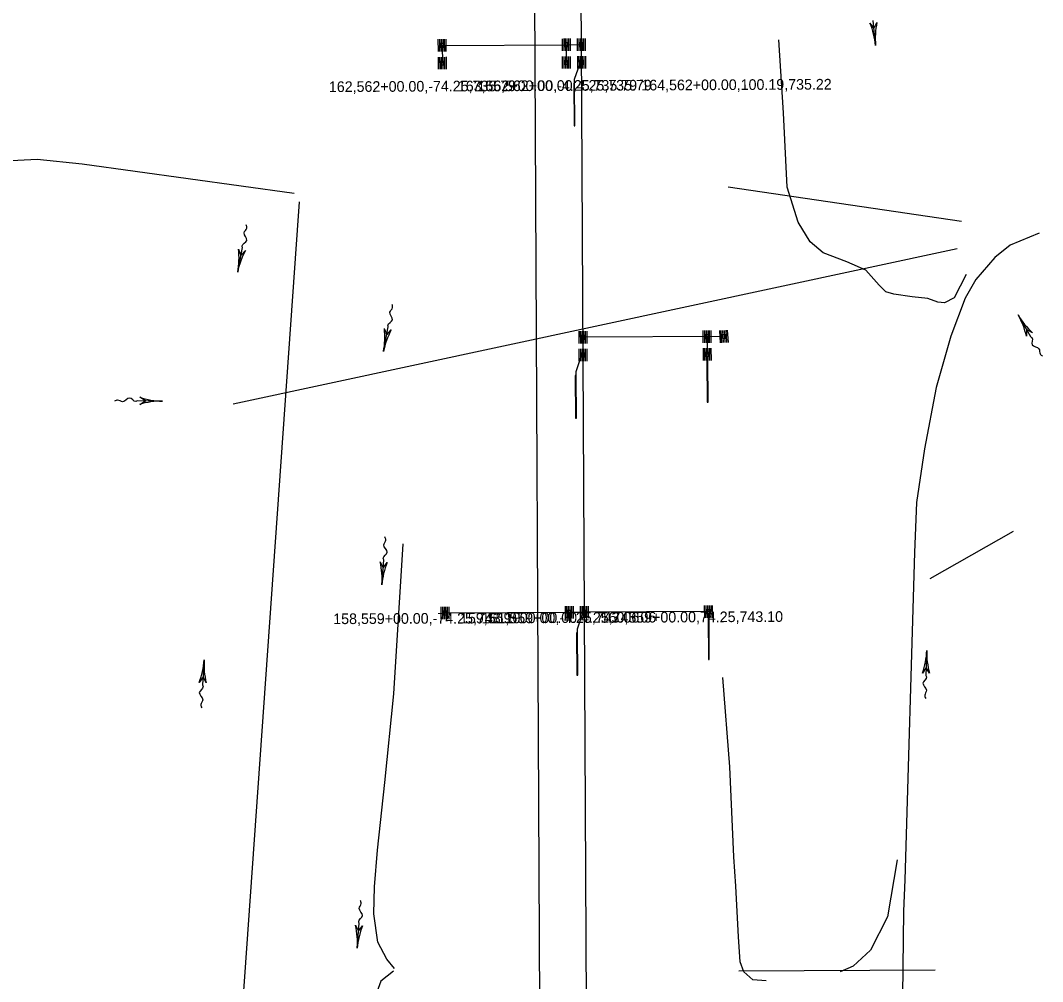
# Model space of a CAD drawing. Extents: x 593481 to 595859, y 101157 to 225994.
# Drawn here: x 594039 to 594615, y 154967 to 155509 of the extents above; entities that cross this region are included whole.
import ezdxf

# ---------------------------------------------------------------- set-up
doc = ezdxf.new("R2010")
doc.units = 0
for name, color, linetype in [('Default', 7, 'Continuous'), ('E_DTM_SpotElev', 7, 'Continuous'), ('E_PROF_GridMin', 7, 'Continuous'), ('Level 6', 7, 'Continuous'), ('P_DRN_SS_UG', 7, 'Continuous'), ('P_MAP_ContoursInter', 7, 'Continuous')]:
    doc.layers.add(name, color=color, linetype=linetype)

msp = doc.modelspace()

# ---------------------------------------------------------------- linework, layer by layer
at = {"layer": 'Default'}
msp.add_line((594334.5, 154382.75), (594308.82, 159385.62), dxfattribs=at)
at = {"layer": 'E_DTM_SpotElev'}
for p, q in [((594520.8, 155494.83), (594519.46, 155508.9)), ((594161.19, 155367.03), (594163.89, 155380.89)), ((594601.12, 155342.88), (594608.19, 155330.65)), ((594243.38, 155322.25), (594246.08, 155336.12)), ((594118.75, 155294.28), (594104.62, 155294.42)), ((594242.48, 155190.75), (594243.54, 155204.84)), ((594549.65, 155153.69), (594549.17, 155139.57)), ((594142.3, 155148.35), (594141.41, 155134.25)), ((594228.61, 154985.82), (594229.67, 154999.91))]:
    msp.add_line(p, q, dxfattribs=at)
for points in [[(594517.6, 155507.38), (594519.89, 155504.38), (594521.58, 155507.76)], [(594161.67, 155379.97), (594163.02, 155376.45), (594165.59, 155379.21)], [(594243.86, 155335.19), (594245.21, 155331.67), (594247.79, 155334.43)], [(594609.26, 155332.81), (594605.93, 155334.58), (594605.8, 155330.8)], [(594105.94, 155292.41), (594109.16, 155294.38), (594105.97, 155296.41)], [(594241.45, 155203.66), (594243.2, 155200.32), (594245.44, 155203.37)], [(594551.21, 155140.83), (594549.32, 155144.1), (594547.22, 155140.96)], [(594143.49, 155135.45), (594141.7, 155138.77), (594139.5, 155135.7)], [(594227.57, 154998.73), (594229.32, 154995.39), (594231.56, 154998.44)]]:
    msp.add_lwpolyline(points, dxfattribs=at)
for centre, start, end in [((594479.03, 155490.87), 5.41261, 23.17493), ((594562.57, 155498.79), 167.65029, 185.41261), ((594120, 155375.03), 349.00666, 6.76898), ((594202.38, 155359.02), 151.24434, 169.00666), ((594637.44, 155363.89), 210.05001, 227.81233), ((594564.8, 155321.87), 12.2877, 30.05001), ((594202.2, 155330.25), 349.00666, 6.76898), ((594284.57, 155314.25), 151.24434, 169.00666), ((594118.34, 155252.33), 89.4352, 107.19752), ((594119.17, 155336.24), 251.67288, 269.4352), ((594200.65, 155193.9), 355.6942, 13.45652), ((594284.32, 155187.6), 157.93188, 175.6942), ((594507.72, 155155.12), 340.28381, 358.04613), ((594591.58, 155152.26), 178.04613, 195.80845), ((594100.43, 155151), 338.61546, 356.37778), ((594184.17, 155145.7), 176.37778, 194.1401), ((594186.77, 154988.97), 355.6942, 13.45652), ((594270.44, 154982.67), 157.93188, 175.6942)]:
    msp.add_arc(centre, 41.96, start, end, dxfattribs=at)
for points in [[(594163.89, 155380.9), (594163.73, 155381.73), (594166.26, 155384.91), (594164.86, 155389.18), (594166.32, 155391.78), (594166.03, 155393.59)], [(594246.08, 155336.12), (594245.92, 155336.95), (594248.46, 155340.13), (594247.05, 155344.4), (594248.51, 155347), (594248.22, 155348.81)], [(594608.19, 155330.65), (594608.86, 155330.13), (594609.04, 155326.06), (594612.9, 155323.76), (594613.5, 155320.85), (594614.91, 155319.67)], [(594104.62, 155294.42), (594103.84, 155294.12), (594100.24, 155296.03), (594096.3, 155293.88), (594093.48, 155294.85), (594091.75, 155294.24)], [(594243.54, 155204.84), (594243.29, 155205.65), (594245.44, 155209.11), (594243.54, 155213.19), (594244.69, 155215.93), (594244.2, 155217.7)], [(594549.17, 155139.57), (594549.45, 155138.77), (594547.45, 155135.23), (594549.51, 155131.23), (594548.47, 155128.44), (594549.04, 155126.69)], [(594141.41, 155134.25), (594141.67, 155133.44), (594139.56, 155129.96), (594141.51, 155125.9), (594140.39, 155123.14), (594140.91, 155121.38)], [(594229.67, 154999.91), (594229.41, 155000.72), (594231.56, 155004.18), (594229.67, 155008.26), (594230.82, 155011), (594230.32, 155012.77)]]:
    msp.add_spline(points, degree=3, dxfattribs=at)
at = {"layer": 'E_PROF_GridMin'}
for p, q in [((594355.04, 155495.24), (594353.62, 155771.98)), ((594276.54, 155494.84), (594346.54, 155495.2)), ((594276.54, 155494.84), (594276.59, 155484.84)), ((594346.54, 155495.2), (594355.04, 155495.24)), ((594346.59, 155485.2), (594346.54, 155495.2)), ((594356.68, 155175.25), (594355.04, 155495.24)), ((594434.34, 155330.65), (594355.89, 155330.24)), ((594425.94, 155330.6), (594425.94, 155320.6)), ((594425.96, 155319.64), (594425.97, 155317.64)), ((594278.18, 155174.84), (594348.18, 155175.2)), ((594348.18, 155175.2), (594356.68, 155175.25)), ((594426.68, 155175.61), (594356.68, 155175.25)), ((594358.22, 154875.25), (594356.68, 155175.25)), ((594426.69, 155174.61), (594426.7, 155172.61))]:
    msp.add_line(p, q, dxfattribs=at)
for points in [[(594571.92, 155365.74), (594565.14, 155352.43), (594559.64, 155349.73), (594555.87, 155350.12), (594550.25, 155352.04), (594541.37, 155353.15), (594531.15, 155354.6), (594526.59, 155355.9), (594522.9, 155359.56), (594515.29, 155368.06), (594504.61, 155372.79), (594491.24, 155377.87), (594483.84, 155384), (594477.1, 155395.15), (594470.86, 155414.95), (594468.94, 155456.73), (594466.21, 155498.03)], [(594353.8, 155484.07), (594350.89, 155475.55), (594350.9, 155473.55)], [(594193.09, 155411.34), (594073.54, 155427.86), (594048.1, 155430.58), (594022.56, 155429.15), (594004.52, 155425.45), (593990.2, 155419.58), (593976.72, 155409.53), (593963.18, 155397.41), (593953.35, 155382.07), (593943.75, 155338.68), (593941.24, 155313.82), (593931.56, 155304.71), (593921.12, 155302.9), (593896.63, 155305.59), (593891.96, 155307.79), (593879.74, 155310.17), (593860.02, 155314.83), (593844.02, 155317.31), (593827.14, 155321.89), (593814.99, 155327.39)], [(594195.87, 155406.63), (594155.86, 154839.17), (594136.12, 154647.32), (594125.75, 154586.3), (594119.28, 154562.31), (594104.8, 154521.76), (594093.35, 154507.25), (594075.71, 154498.55), (594048.65, 154492.71), (593981.57, 154485.26), (593546.85, 154493.19), (593538.17, 154494.28), (593526.38, 154497.62), (593514.24, 154502.72), (593501.23, 154504.79), (593491.32, 154504.17), (593484.5, 154500.86), (593481.17, 154494.41)], [(594612.95, 155388.89), (594596.71, 155382.2), (594588.1, 155375.16), (594577.39, 155362.81), (594571.35, 155352.38), (594563.26, 155330.97), (594554.94, 155301.9), (594548.34, 155267.44), (594543.77, 155237.13), (594542.73, 155208.88), (594537.26, 155024.38), (594536.51, 155006.73), (594535.72, 154943.23), (594533.09, 154881.6), (594531.45, 154816.64), (594529.67, 154746.17)], [(594354.6, 155319.27), (594351.74, 155310.74), (594351.75, 155308.74)], [(594249.5, 154974.47), (594245.36, 154979.68), (594240.25, 154989.23), (594237.97, 155005.19), (594238.36, 155020.5), (594239.95, 155041.07), (594244.13, 155079.25), (594249.14, 155129.18), (594254.49, 155213.86)], [(594355.34, 155174.22), (594352.48, 155165.69), (594352.49, 155163.69)], [(594459.03, 154967.51), (594451.56, 154968.01), (594446.5, 154972.57), (594444.41, 154978.14), (594443.43, 154992.33), (594442.07, 155020.78), (594440.92, 155037.43), (594438.56, 155088.15), (594434.63, 155138.37)], [(594532.95, 155035.61), (594527.56, 155003.52), (594517.93, 154984.63), (594508.17, 154975.76), (594500.89, 154972.46)], [(594248.94, 154972.9), (594241.91, 154967.19), (594238.79, 154958.94), (594235.75, 154930.84), (594230.88, 154901.44), (594227.52, 154859.43), (594221.1, 154817.5), (594214.83, 154781.45), (594209.84, 154735.27), (594200.1, 154653.01), (594191.65, 154590.92), (594189.63, 154541.3), (594190.82, 154497.49), (594193.99, 154473.57)]]:
    msp.add_lwpolyline(points, dxfattribs=at)
at = {"layer": 'P_DRN_SS_UG'}
for p, q in [((594274.31, 155491.39), (594274.27, 155498.26)), ((594275.21, 155491.39), (594275.17, 155498.27)), ((594276.11, 155491.4), (594276.07, 155498.27)), ((594277.01, 155491.4), (594276.97, 155498.28)), ((594277.91, 155491.41), (594277.87, 155498.28)), ((594278.81, 155491.41), (594278.77, 155498.29)), ((594344.31, 155491.75), (594344.27, 155498.62)), ((594345.21, 155491.75), (594345.17, 155498.63)), ((594346.11, 155491.76), (594346.07, 155498.63)), ((594347.01, 155491.76), (594346.97, 155498.64)), ((594347.91, 155491.77), (594347.87, 155498.64)), ((594348.81, 155491.77), (594348.77, 155498.65)), ((594352.81, 155491.79), (594352.77, 155498.67)), ((594353.71, 155491.8), (594353.67, 155498.67)), ((594354.61, 155491.8), (594354.57, 155498.68)), ((594355.51, 155491.81), (594355.47, 155498.68)), ((594356.41, 155491.81), (594356.37, 155498.69)), ((594357.31, 155491.82), (594357.27, 155498.69)), ((594344.36, 155481.75), (594344.32, 155488.62)), ((594345.26, 155481.75), (594345.22, 155488.63)), ((594346.16, 155481.76), (594346.12, 155488.63)), ((594347.06, 155481.76), (594347.02, 155488.64)), ((594347.96, 155481.77), (594347.92, 155488.64)), ((594348.86, 155481.77), (594348.82, 155488.65)), ((594352.91, 155481.8), (594352.87, 155488.68)), ((594353.81, 155481.81), (594353.77, 155488.68)), ((594354.71, 155481.81), (594354.67, 155488.69)), ((594355.61, 155481.82), (594355.57, 155488.69)), ((594356.51, 155481.82), (594356.47, 155488.7)), ((594357.41, 155481.83), (594357.37, 155488.7)), ((594274.36, 155481.39), (594274.32, 155488.26)), ((594275.26, 155481.39), (594275.22, 155488.27)), ((594276.16, 155481.4), (594276.12, 155488.27)), ((594277.06, 155481.4), (594277.02, 155488.28)), ((594277.96, 155481.41), (594277.92, 155488.28)), ((594278.86, 155481.41), (594278.82, 155488.29)), ((594353.65, 155326.8), (594353.62, 155333.67)), ((594354.55, 155326.8), (594354.52, 155333.67)), ((594355.45, 155326.8), (594355.42, 155333.68)), ((594356.35, 155326.81), (594356.32, 155333.68)), ((594357.25, 155326.81), (594357.22, 155333.69)), ((594358.15, 155326.82), (594358.12, 155333.69)), ((594423.65, 155327.15), (594423.62, 155334.03)), ((594424.55, 155327.16), (594424.52, 155334.03)), ((594425.45, 155327.16), (594425.42, 155334.04)), ((594426.35, 155327.17), (594426.32, 155334.04)), ((594427.25, 155327.17), (594427.22, 155334.05)), ((594428.15, 155327.18), (594428.12, 155334.05)), ((594433.28, 155327.15), (594432.9, 155334.01)), ((594434.18, 155327.2), (594433.8, 155334.06)), ((594435.08, 155327.24), (594434.7, 155334.11)), ((594435.98, 155327.29), (594435.6, 155334.16)), ((594436.88, 155327.34), (594436.5, 155334.21)), ((594437.78, 155327.39), (594437.4, 155334.26)), ((594353.71, 155316.81), (594353.68, 155323.68)), ((594354.61, 155316.81), (594354.58, 155323.68)), ((594355.51, 155316.81), (594355.48, 155323.69)), ((594356.41, 155316.82), (594356.38, 155323.69)), ((594357.31, 155316.82), (594357.28, 155323.7)), ((594358.21, 155316.83), (594358.18, 155323.7)), ((594423.72, 155317.19), (594423.69, 155324.07)), ((594424.62, 155317.2), (594424.59, 155324.07)), ((594425.52, 155317.2), (594425.49, 155324.08)), ((594426.42, 155317.21), (594426.39, 155324.08)), ((594427.32, 155317.21), (594427.29, 155324.09)), ((594428.22, 155317.22), (594428.19, 155324.09)), ((594275.95, 155171.39), (594275.91, 155178.27)), ((594276.85, 155171.4), (594276.81, 155178.27)), ((594277.75, 155171.4), (594277.71, 155178.28)), ((594278.65, 155171.41), (594278.61, 155178.28)), ((594279.55, 155171.41), (594279.51, 155178.29)), ((594280.45, 155171.42), (594280.41, 155178.29)), ((594345.95, 155171.75), (594345.91, 155178.63)), ((594346.85, 155171.76), (594346.81, 155178.63)), ((594347.75, 155171.76), (594347.71, 155178.64)), ((594348.65, 155171.77), (594348.61, 155178.64)), ((594349.55, 155171.77), (594349.51, 155178.65)), ((594350.45, 155171.78), (594350.41, 155178.65)), ((594354.45, 155171.8), (594354.41, 155178.67)), ((594355.35, 155171.8), (594355.31, 155178.68)), ((594356.25, 155171.81), (594356.21, 155178.68)), ((594357.15, 155171.81), (594357.11, 155178.69)), ((594358.05, 155171.82), (594358.01, 155178.69)), ((594358.95, 155171.82), (594358.91, 155178.69)), ((594424.45, 155172.16), (594424.41, 155179.03)), ((594425.35, 155172.16), (594425.31, 155179.04)), ((594426.25, 155172.17), (594426.21, 155179.04)), ((594427.15, 155172.17), (594427.11, 155179.05)), ((594428.05, 155172.17), (594428.01, 155179.05)), ((594428.95, 155172.18), (594428.91, 155179.05))]:
    msp.add_line(p, q, dxfattribs=at)
for points in [[(594277.55, 155493.84), (594277.53, 155495.84), (594275.53, 155495.83), (594275.55, 155493.83)], [(594347.54, 155494.2), (594347.53, 155496.2), (594345.53, 155496.19), (594345.54, 155494.19)], [(594356.04, 155494.25), (594356.03, 155496.25), (594354.03, 155496.24), (594354.04, 155494.24)], [(594277.6, 155483.84), (594277.59, 155485.84), (594275.59, 155485.83), (594275.6, 155483.83)], [(594347.6, 155484.2), (594347.59, 155486.2), (594345.59, 155486.19), (594345.6, 155484.19)], [(594356.15, 155484.26), (594356.13, 155486.26), (594354.13, 155486.25), (594354.15, 155484.25)], [(594350.79, 155449.55), (594351.26, 155449.55), (594351.14, 155473.55), (594350.66, 155473.55)], [(594356.89, 155329.25), (594356.88, 155331.25), (594354.88, 155331.24), (594354.89, 155329.24)], [(594426.89, 155329.61), (594426.88, 155331.61), (594424.88, 155331.6), (594424.89, 155329.6)], [(594436.39, 155329.76), (594436.28, 155331.75), (594434.29, 155331.65), (594434.4, 155329.65)], [(594426.96, 155319.65), (594426.95, 155321.65), (594424.95, 155321.64), (594424.96, 155319.64)], [(594356.95, 155319.26), (594356.94, 155321.26), (594354.94, 155321.25), (594354.95, 155319.25)], [(594425.86, 155293.64), (594426.33, 155293.64), (594426.21, 155317.64), (594425.73, 155317.64)], [(594351.63, 155284.74), (594352.11, 155284.74), (594351.98, 155308.74), (594351.51, 155308.74)], [(594279.19, 155173.85), (594279.18, 155175.85), (594277.18, 155175.84), (594277.19, 155173.84)], [(594349.19, 155174.21), (594349.18, 155176.21), (594347.18, 155176.2), (594347.19, 155174.2)], [(594357.69, 155174.25), (594357.68, 155176.25), (594355.68, 155176.24), (594355.69, 155174.24)], [(594427.69, 155174.61), (594427.68, 155176.61), (594425.68, 155176.6), (594425.69, 155174.6)], [(594426.58, 155148.6), (594427.06, 155148.61), (594426.93, 155172.61), (594426.46, 155172.6)], [(594352.38, 155139.68), (594352.85, 155139.69), (594352.73, 155163.69), (594352.25, 155163.68)]]:
    msp.add_lwpolyline(points, close=True, dxfattribs=at)
at = {"layer": 'P_MAP_ContoursInter'}
for p, q in [((594437.6, 155415.01), (594569.29, 155395.66)), ((594158.67, 155292.68), (594566.79, 155380.23)), ((594551.54, 155194.26), (594598.53, 155220.88)), ((594443.69, 154973.11), (594554.46, 154973.67))]:
    msp.add_line(p, q, dxfattribs=at)

# ---------------------------------------------------------------- texts
at = {"layer": 'Level 6'}
for s, p in [('162,562+00.00,-74.25,735.79', (594212.62, 155468.51)), ('163,562+00.00,-4.25,735.79', (594285.31, 155468.88)), ('165,562+00.00,4.25,735.79', (594296.26, 155468.94)), ('164,562+00.00,100.19,735.22', (594388.75, 155469.41)), ('158,559+00.00,-74.25,743.10', (594215.08, 155168.52)), ('159,559+00.00,-4.25,743.06', (594286.52, 155168.89)), ('161,559+00.00,4.25,743.06', (594298.75, 155168.95)), ('160,559+00.00,74.25,743.10', (594365.79, 155169.29))]:
    msp.add_text(s, height=6, rotation=0.29409, dxfattribs=at).set_placement(p)

doc.saveas('drawing.dxf')
